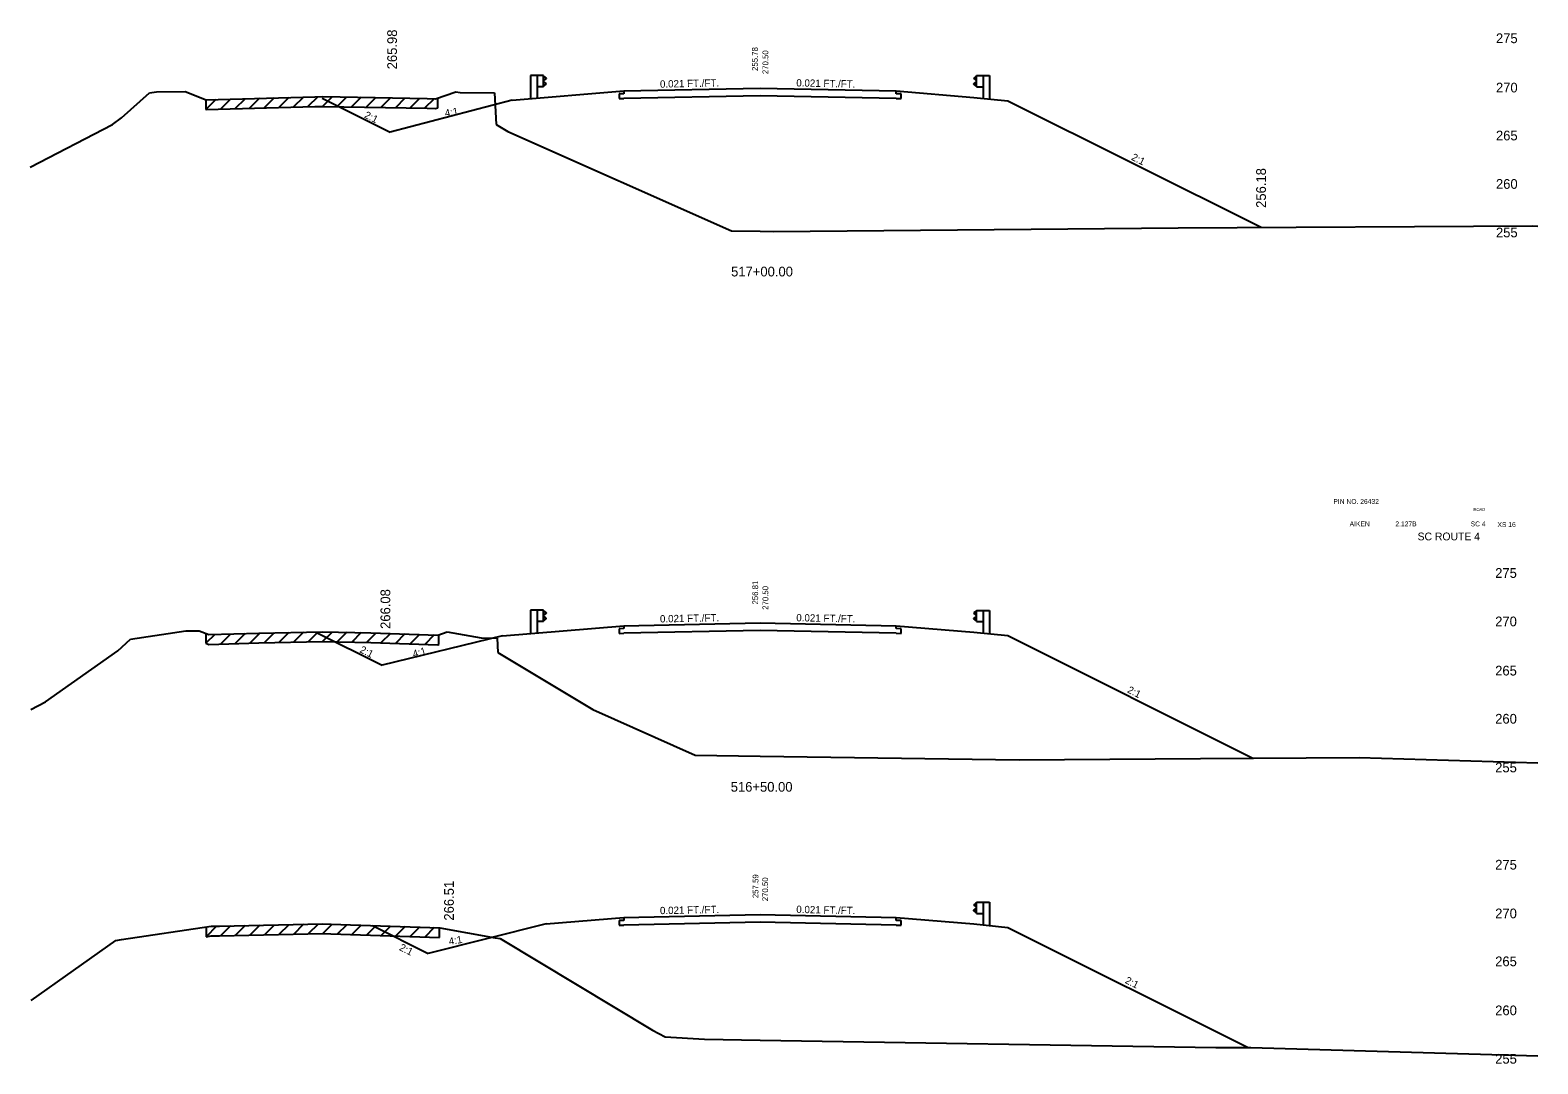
# Model space of a CAD drawing. Extents: x 883 to 1160, y 1002 to 4323.
# Drawn here: x 1004.9 to 1160, y 2770.2 to 2876.5 of the extents above; entities that cross this region are included whole.
import ezdxf

# ---------------------------------------------------------------- set-up
doc = ezdxf.new("R2010")
doc.units = 0
for name, color, linetype in [('Level 1', 7, 'Continuous'), ('Level 10', 7, 'Continuous'), ('Level 11', 7, 'Continuous'), ('Level 12', 7, 'Continuous'), ('Level 24', 7, 'Continuous'), ('Level 3', 7, 'Continuous'), ('Level 32', 7, 'Continuous'), ('Level 33', 7, 'Continuous'), ('Level 59', 7, 'Continuous'), ('Level 6', 7, 'Continuous'), ('Level 60', 7, 'Continuous'), ('Level 61', 7, 'Continuous'), ('Level 7', 7, 'Continuous')]:
    doc.layers.add(name, color=color, linetype=linetype)

msp = doc.modelspace()

# ---------------------------------------------------------------- linework, layer by layer
at = {"layer": 'Level 11'}
for p, q in [((1066, 2869.91), (1065.5, 2869.9)), ((1065.5, 2869.9), (1065.5, 2869.42)), ((1065.5, 2869.42), (1066, 2869.43)), ((1066, 2870.21), (1066, 2869.91)), ((1094, 2869.91), (1094, 2870.21)), ((1094.5, 2869.9), (1094, 2869.91)), ((1094, 2869.43), (1094.5, 2869.42)), ((1094.5, 2869.42), (1094.5, 2869.9)), ((1066, 2814.91), (1065.5, 2814.9)), ((1065.5, 2814.9), (1065.5, 2814.42)), ((1066, 2815.21), (1066, 2814.91)), ((1094, 2814.91), (1094, 2815.21)), ((1094.5, 2814.9), (1094, 2814.91)), ((1094.5, 2814.42), (1094.5, 2814.9)), ((1065.5, 2814.42), (1066, 2814.43)), ((1094, 2814.43), (1094.5, 2814.42)), ((1066, 2784.91), (1065.5, 2784.9)), ((1065.5, 2784.9), (1065.5, 2784.42)), ((1065.5, 2784.42), (1066, 2784.43)), ((1066, 2785.21), (1066, 2784.91)), ((1094, 2784.91), (1094, 2785.21)), ((1094.5, 2784.9), (1094, 2784.91)), ((1094, 2784.43), (1094.5, 2784.42)), ((1094.5, 2784.42), (1094.5, 2784.9))]:
    msp.add_line(p, q, dxfattribs=at)
at = {"layer": 'Level 12'}
for p, q in [((1080, 2869.72), (1066, 2869.43)), ((1094, 2869.43), (1080, 2869.72)), ((1080, 2814.72), (1066, 2814.43)), ((1094, 2814.43), (1080, 2814.72)), ((1080, 2784.72), (1066, 2784.43)), ((1094, 2784.43), (1080, 2784.72))]:
    msp.add_line(p, q, dxfattribs=at)
at = {"layer": 'Level 24'}
for p, q in [((1056.4, 2871.8), (1056.4, 2869.39)), ((1057.07, 2871.8), (1056.4, 2871.8)), ((1057.73, 2871.8), (1057.07, 2871.8)), ((1057.07, 2871.8), (1057.07, 2869.46)), ((1057.73, 2870.64), (1057.07, 2870.64)), ((1057.73, 2870.64), (1057.73, 2871.8)), ((1057.73, 2871.73), (1058, 2871.53)), ((1058, 2871.48), (1057.73, 2871.28)), ((1058, 2870.96), (1057.73, 2871.16)), ((1057.73, 2870.71), (1058, 2870.91)), ((1058, 2871.53), (1058, 2871.48)), ((1058, 2870.91), (1058, 2870.96)), ((1102.27, 2871.72), (1102, 2871.52)), ((1102, 2871.52), (1102, 2871.47)), ((1102, 2871.47), (1102.27, 2871.27)), ((1102, 2870.95), (1102.27, 2871.15)), ((1102, 2870.9), (1102, 2870.95)), ((1102.27, 2870.7), (1102, 2870.9)), ((1102.27, 2870.63), (1102.27, 2871.79)), ((1102.27, 2871.79), (1102.94, 2871.79)), ((1102.27, 2870.63), (1102.94, 2870.63)), ((1102.94, 2871.79), (1102.94, 2869.45)), ((1102.94, 2871.79), (1103.6, 2871.79)), ((1103.6, 2871.79), (1103.6, 2869.38)), ((1056.4, 2816.81), (1056.4, 2814.4)), ((1057.07, 2816.81), (1056.4, 2816.81)), ((1057.73, 2816.81), (1057.07, 2816.81)), ((1057.07, 2816.81), (1057.07, 2814.47)), ((1057.73, 2815.64), (1057.73, 2816.81)), ((1057.73, 2816.74), (1058, 2816.54)), ((1058, 2816.49), (1057.73, 2816.29)), ((1058, 2816.54), (1058, 2816.49)), ((1102.27, 2816.72), (1102, 2816.52)), ((1102, 2816.52), (1102, 2816.47)), ((1102, 2816.47), (1102.27, 2816.27)), ((1102.27, 2815.63), (1102.27, 2816.79)), ((1102.27, 2816.79), (1102.94, 2816.79)), ((1102.94, 2816.79), (1102.94, 2814.45)), ((1102.94, 2816.79), (1103.6, 2816.79)), ((1103.6, 2816.79), (1103.6, 2814.38)), ((1057.73, 2815.64), (1057.07, 2815.64)), ((1058, 2815.97), (1057.73, 2816.17)), ((1057.73, 2815.72), (1058, 2815.92)), ((1058, 2815.92), (1058, 2815.97)), ((1102, 2815.95), (1102.27, 2816.15)), ((1102, 2815.9), (1102, 2815.95)), ((1102.27, 2815.7), (1102, 2815.9)), ((1102.27, 2815.63), (1102.94, 2815.63)), ((1102.27, 2785.63), (1102.27, 2786.79)), ((1102.27, 2786.79), (1102.94, 2786.79)), ((1102.94, 2786.79), (1102.94, 2784.45)), ((1102.94, 2786.79), (1103.6, 2786.79)), ((1103.6, 2786.79), (1103.6, 2784.38)), ((1102.27, 2786.72), (1102, 2786.52)), ((1102, 2786.52), (1102, 2786.47)), ((1102, 2786.47), (1102.27, 2786.27)), ((1102, 2785.95), (1102.27, 2786.15)), ((1102, 2785.9), (1102, 2785.95)), ((1102.27, 2785.7), (1102, 2785.9)), ((1102.27, 2785.63), (1102.94, 2785.63))]:
    msp.add_line(p, q, dxfattribs=at)
at = {"layer": 'Level 59'}
for p, q in [((1066, 2870.21), (1080, 2870.5)), ((1080, 2870.5), (1094, 2870.21)), ((1066, 2815.21), (1080, 2815.5)), ((1080, 2815.5), (1094, 2815.21)), ((1066, 2785.21), (1080, 2785.5)), ((1080, 2785.5), (1094, 2785.21))]:
    msp.add_line(p, q, dxfattribs=at)
at = {"layer": 'Level 6'}
for p, q in [((1054.5, 2869.25), (1066, 2870.21)), ((1094, 2870.21), (1102, 2869.54)), ((1102, 2869.54), (1105.5, 2869.19)), ((1053.5, 2814.17), (1066, 2815.21)), ((1094, 2815.21), (1102, 2814.54)), ((1102, 2814.54), (1105.5, 2814.19)), ((1058, 2784.54), (1066, 2785.21)), ((1094, 2785.21), (1102, 2784.54)), ((1102, 2784.54), (1105.5, 2784.19))]:
    msp.add_line(p, q, dxfattribs=at)
at = {"layer": 'Level 60'}
for p, q in [((1014.32, 2867.43), (1017.18, 2870)), ((1017.18, 2870), (1017.91, 2870.11)), ((1017.91, 2870.11), (1020.87, 2870.15)), ((1020.87, 2870.15), (1023.01, 2869.29)), ((1023.01, 2869.29), (1034.2, 2869.61)), ((1034.2, 2869.61), (1035.02, 2869.62)), ((1035.02, 2869.62), (1045.76, 2869.42)), ((1045.76, 2869.42), (1046.6, 2869.39)), ((1046.6, 2869.39), (1048.72, 2870.13)), ((1048.72, 2870.13), (1049.15, 2870.06)), ((1049.15, 2870.06), (1052.67, 2870.01)), ((1052.67, 2870.01), (1052.85, 2866.76)), ((1004.92, 2862.36), (1013.38, 2866.76)), ((1013.38, 2866.76), (1014.32, 2867.43)), ((1052.85, 2866.76), (1054.06, 2866.03)), ((1054.06, 2866.03), (1077.07, 2855.82)), ((1077.07, 2855.82), (1080, 2855.78)), ((1080, 2855.78), (1081.39, 2855.76)), ((1081.39, 2855.76), (1122.99, 2856.13)), ((1122.99, 2856.13), (1159.46, 2856.32)), ((1159.46, 2856.32), (1160, 2856.3)), ((1013.93, 2812.63), (1015.25, 2813.82)), ((1015.25, 2813.82), (1020.95, 2814.67)), ((1020.95, 2814.67), (1022.31, 2814.69)), ((1022.31, 2814.69), (1023.29, 2814.29)), ((1023.29, 2814.29), (1028.44, 2814.44)), ((1028.44, 2814.44), (1035, 2814.57)), ((1035, 2814.57), (1039.95, 2814.48)), ((1039.95, 2814.48), (1046.84, 2814.25)), ((1046.84, 2814.25), (1047.82, 2814.59)), ((1047.82, 2814.59), (1051.32, 2813.96)), ((1051.32, 2813.96), (1052.95, 2813.94)), ((1052.95, 2813.94), (1053.03, 2812.44)), ((1006.51, 2807.38), (1013.93, 2812.63)), ((1053.03, 2812.44), (1062.8, 2806.59)), ((1005, 2806.59), (1006.51, 2807.38)), ((1062.8, 2806.59), (1073.33, 2801.91)), ((1073.33, 2801.91), (1080, 2801.81)), ((1080, 2801.81), (1106.66, 2801.4)), ((1106.66, 2801.4), (1125.29, 2801.57)), ((1125.29, 2801.57), (1141.62, 2801.66)), ((1141.62, 2801.66), (1160, 2801.12)), ((1014.31, 2782.93), (1023.53, 2784.3)), ((1023.53, 2784.3), (1024.38, 2784.31)), ((1024.38, 2784.31), (1034.99, 2784.54)), ((1034.99, 2784.54), (1035.85, 2784.51)), ((1035.85, 2784.51), (1047.05, 2784.14)), ((1047.05, 2784.14), (1052.74, 2783.12)), ((1005.03, 2776.68), (1013.74, 2782.85)), ((1013.74, 2782.85), (1014.31, 2782.93)), ((1052.74, 2783.12), (1053.25, 2783.03)), ((1053.25, 2783.03), (1068.94, 2773.62)), ((1068.94, 2773.62), (1070.25, 2772.92)), ((1070.25, 2772.92), (1074.27, 2772.69)), ((1074.27, 2772.69), (1080, 2772.59)), ((1080, 2772.59), (1126.87, 2771.84)), ((1126.87, 2771.84), (1130.48, 2771.83)), ((1130.48, 2771.83), (1160, 2770.98))]:
    msp.add_line(p, q, dxfattribs=at)
at = {"layer": 'Level 61'}
for p, q in [((1024.01, 2869.32), (1022.99, 2868.3)), ((1022.99, 2869.3), (1022.99, 2868.3)), ((1025.52, 2869.36), (1024.49, 2868.33)), ((1027.02, 2869.4), (1025.99, 2868.37)), ((1028.52, 2869.45), (1027.49, 2868.42)), ((1030.02, 2869.49), (1028.99, 2868.46)), ((1031.52, 2869.53), (1030.49, 2868.5)), ((1033.02, 2869.57), (1031.99, 2868.54)), ((1034.51, 2869.61), (1033.49, 2868.59)), ((1035.97, 2869.6), (1034.99, 2868.62)), ((1037.47, 2869.58), (1036.49, 2868.59)), ((1038.97, 2869.55), (1037.99, 2868.57)), ((1040.47, 2869.52), (1039.49, 2868.54)), ((1041.97, 2869.49), (1040.99, 2868.51)), ((1043.47, 2869.46), (1042.49, 2868.48)), ((1044.97, 2869.43), (1043.99, 2868.45)), ((1046.46, 2869.4), (1045.49, 2868.42)), ((1046.86, 2868.48), (1046.86, 2869.48)), ((1022.99, 2868.3), (1023.01, 2868.29)), ((1023.01, 2868.29), (1034.2, 2868.61)), ((1034.2, 2868.61), (1035.02, 2868.62)), ((1035.02, 2868.62), (1045.76, 2868.42)), ((1045.76, 2868.42), (1046.6, 2868.39)), ((1046.6, 2868.39), (1046.86, 2868.48)), ((1023, 2814.41), (1023, 2813.41)), ((1023.9, 2814.31), (1023, 2813.41)), ((1023, 2813.41), (1023.29, 2813.29)), ((1023.29, 2813.29), (1028.44, 2813.44)), ((1025.53, 2814.35), (1024.5, 2813.32)), ((1027.03, 2814.4), (1026, 2813.37)), ((1028.53, 2814.44), (1027.5, 2813.41)), ((1028.44, 2813.44), (1035, 2813.57)), ((1030.02, 2814.47), (1029, 2813.45)), ((1031.52, 2814.5), (1030.5, 2813.48)), ((1033.02, 2814.53), (1032, 2813.51)), ((1034.52, 2814.56), (1033.5, 2813.54)), ((1035.98, 2814.55), (1035, 2813.57)), ((1035, 2813.57), (1039.95, 2813.48)), ((1037.48, 2814.53), (1036.5, 2813.54)), ((1038.98, 2814.5), (1038, 2813.52)), ((1040.47, 2814.46), (1039.5, 2813.49)), ((1039.95, 2813.48), (1046.84, 2813.25)), ((1041.97, 2814.41), (1041, 2813.44)), ((1043.47, 2814.36), (1042.5, 2813.39)), ((1044.97, 2814.31), (1044, 2813.34)), ((1046.47, 2814.26), (1045.5, 2813.29)), ((1046.84, 2813.25), (1046.94, 2813.28)), ((1046.94, 2813.28), (1046.94, 2814.28)), ((1024.1, 2784.31), (1023.01, 2783.22)), ((1023.01, 2784.22), (1023.01, 2783.22)), ((1025.53, 2784.34), (1024.51, 2783.32)), ((1027.03, 2784.37), (1026.01, 2783.35)), ((1028.53, 2784.4), (1027.51, 2783.38)), ((1030.03, 2784.43), (1029.01, 2783.41)), ((1031.53, 2784.46), (1030.51, 2783.44)), ((1033.03, 2784.5), (1032.01, 2783.47)), ((1034.53, 2784.53), (1033.51, 2783.51)), ((1035.98, 2784.51), (1035.01, 2783.54)), ((1037.48, 2784.46), (1036.51, 2783.49)), ((1038.98, 2784.41), (1038.01, 2783.44)), ((1040.48, 2784.36), (1039.51, 2783.39)), ((1041.98, 2784.31), (1041.01, 2783.34)), ((1043.48, 2784.26), (1042.51, 2783.29)), ((1044.98, 2784.21), (1044.01, 2783.24)), ((1046.48, 2784.16), (1045.51, 2783.19)), ((1047.02, 2783.14), (1047.02, 2784.14)), ((1023.01, 2783.22), (1023.53, 2783.3)), ((1023.53, 2783.3), (1024.38, 2783.31)), ((1024.38, 2783.31), (1034.99, 2783.54)), ((1034.99, 2783.54), (1035.85, 2783.51)), ((1035.85, 2783.51), (1047.02, 2783.14))]:
    msp.add_line(p, q, dxfattribs=at)
at = {"layer": 'Level 7'}
for p, q in [((1034.94, 2869.47), (1041.95, 2865.96)), ((1054.5, 2869.25), (1041.95, 2865.96)), ((1105.5, 2869.19), (1131.53, 2856.18)), ((1034.32, 2814.56), (1041.14, 2811.15)), ((1053.5, 2814.17), (1041.14, 2811.15)), ((1105.5, 2814.19), (1130.68, 2801.6)), ((1040.13, 2784.37), (1045.85, 2781.51)), ((1058, 2784.54), (1045.85, 2781.51)), ((1105.5, 2784.19), (1130.22, 2771.83))]:
    msp.add_line(p, q, dxfattribs=at)

# ---------------------------------------------------------------- texts
at = {"layer": 'Level 1'}
for s, height, p in [('517+00.00', 1, (1077.02, 2851.13)), ('PIN NO. 26432', 0.5, (1138.97, 2827.74)), ('AIKEN', 0.5, (1140.64, 2825.43)), (' 2.127B', 0.5, (1145.15, 2825.43)), ('SC 4', 0.5, (1153.09, 2825.43)), ('XS 16', 0.5, (1155.85, 2825.36)), ('SC ROUTE 4', 0.8, (1147.63, 2823.99)), ('516+50.00', 1, (1076.98, 2798.14))]:
    msp.add_text(s, height=height, dxfattribs=at).set_placement(p)
at = {"layer": 'Level 10'}
for s, p in [('255.78', (1079.77, 2872.26)), ('256.81', (1079.8, 2817.39)), ('257.59', (1079.83, 2787.19))]:
    msp.add_text(s, height=0.6, rotation=90, dxfattribs=at).set_placement(p)
at = {"layer": 'Level 3'}
for s, height, p in [(' 275', 1, (1155.32, 2875.12)), (' 270', 1, (1155.32, 2870.05)), (' 265', 1, (1155.32, 2865.12)), (' 260', 1, (1155.32, 2860.14)), (' 255', 1, (1155.32, 2855.15)), ('ROAD', 0.3, (1153.38, 2827.02)), (' 275', 1, (1155.24, 2820.13)), (' 270', 1, (1155.24, 2815.15)), (' 265', 1, (1155.24, 2810.09)), (' 260', 1, (1155.24, 2805.14)), (' 255', 1, (1155.24, 2800.13)), (' 275', 1, (1155.24, 2790.13)), (' 270', 1, (1155.24, 2785.12)), (' 265', 1, (1155.24, 2780.19)), (' 260', 1, (1155.24, 2775.15)), (' 255', 1, (1155.24, 2770.17))]:
    msp.add_text(s, height=height, dxfattribs=at).set_placement(p)
at = {"layer": 'Level 32'}
for s, rotation, p in [('0.021 FT./FT.', 1.1916, (1069.71, 2870.54)), ('0.021 FT./FT.', 358.8084, (1083.72, 2870.67)), ('2:1', 333.435, (1039.22, 2867.49)), ('4:1', 9.4623, (1047.63, 2867.54)), ('2:1', 333.435, (1118.12, 2863.16)), ('0.021 FT./FT.', 1.1916, (1069.71, 2815.54)), ('0.021 FT./FT.', 358.8084, (1083.72, 2815.67)), ('2:1', 333.435, (1038.75, 2812.51)), ('4:1', 15.9089, (1044.38, 2811.92)), ('2:1', 333.435, (1117.7, 2808.37)), ('0.021 FT./FT.', 1.1916, (1069.71, 2785.54)), ('0.021 FT./FT.', 358.8084, (1083.72, 2785.67)), ('2:1', 333.435, (1042.82, 2781.88)), ('4:1', 9.4623, (1048.04, 2782.37)), ('2:1', 333.435, (1117.47, 2778.49))]:
    msp.add_text(s, height=0.75, rotation=rotation, dxfattribs=at).set_placement(p)
at = {"layer": 'Level 33'}
for s, p in [('265.98', (1042.65, 2872.43)), ('256.18', (1132.03, 2858.18)), ('266.08', (1041.96, 2814.88)), ('266.51', (1048.5, 2784.88))]:
    msp.add_text(s, height=1, rotation=90, dxfattribs=at).set_placement(p)
at = {"layer": 'Level 59'}
for p in [(1080.85, 2871.71), (1080.85, 2816.62), (1080.82, 2786.65)]:
    msp.add_text(' 270.50', height=0.6, rotation=90, dxfattribs=at).set_placement(p)

doc.saveas('drawing.dxf')
